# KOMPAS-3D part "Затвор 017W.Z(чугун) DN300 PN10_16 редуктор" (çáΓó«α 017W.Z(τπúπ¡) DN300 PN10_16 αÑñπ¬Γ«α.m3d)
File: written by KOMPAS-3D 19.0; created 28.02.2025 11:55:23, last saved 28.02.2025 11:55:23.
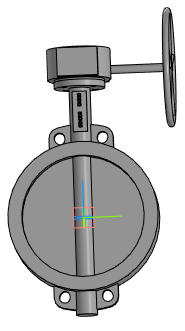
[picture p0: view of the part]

Document properties: Автор: Евгений; Полное имя файла: Затвор 017W.Z(чугун) DN300 PN10_16 редуктор.a3d

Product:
- Part/product: Затвор 017W.Z(чугун) DN300 PN10_16 редуктор
    Масса: 58.8287

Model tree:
1. Операция без истории:1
